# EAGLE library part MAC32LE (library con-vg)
CONNECTOR male, 32 pins, single, type D, rows AC, grid 5.08 mm with mounting clip
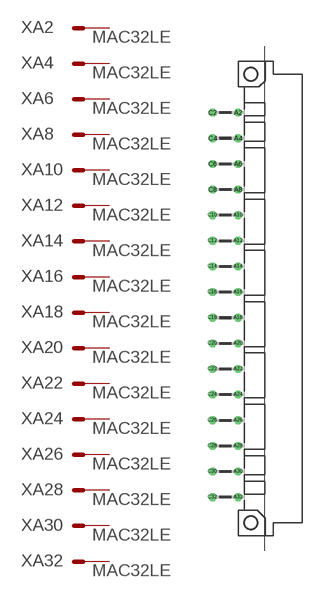
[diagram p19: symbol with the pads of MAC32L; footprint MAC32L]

Designator prefix X; gates A2=M A4=M A6=M A8=M A10=M A12=M A14=M A16=M A18=M A20=M A22=M A24=M A26=M A28=M A30=M A32=M C2=M C4=M C6=M C8=M C10=M C12=M C14=M C16=M C18=M C20=M C22=M C24=M C26=M C28=M C30=M C32=M

## MAC32LE  [MAC32L]
A2  A2:S  pas
A4  A4:S  pas
A6  A6:S  pas
A8  A8:S  pas
A10  A10:S  pas
A12  A12:S  pas
A14  A14:S  pas
A16  A16:S  pas
A18  A18:S  pas
A20  A20:S  pas
A22  A22:S  pas
A24  A24:S  pas
A26  A26:S  pas
A28  A28:S  pas
A30  A30:S  pas
A32  A32:S  pas
C2  C2:S  pas
C4  C4:S  pas
C6  C6:S  pas
C8  C8:S  pas
C10  C10:S  pas
C12  C12:S  pas
C14  C14:S  pas
C16  C16:S  pas
C18  C18:S  pas
C20  C20:S  pas
C22  C22:S  pas
C24  C24:S  pas
C26  C26:S  pas
C28  C28:S  pas
C30  C30:S  pas
C32  C32:S  pas

## Footprint MAC32L (pad centres in mm)
CONNECTOR male, 32 pins, type D, rows AC, grid 5.08 mm with mounting clip
drill 1.016 octagon: A2 -2.54,36.83; A4 -2.54,31.75; A6 -2.54,26.67; A8 -2.54,21.59; A10 -2.54,16.51; A12 -2.54,11.43; A14 -2.54,6.35; A16 -2.54,1.27; A18 -2.54,-3.81; A20 -2.54,-8.89; A22 -2.54,-13.97; A24 -2.54,-19.05; A26 -2.54,-24.13; A28 -2.54,-29.21; A30 -2.54,-34.29; A32 -2.54,-39.37; C2 -7.62,36.83; C4 -7.62,31.75; C6 -7.62,26.67; C8 -7.62,21.59; C10 -7.62,16.51; C12 -7.62,11.43; C14 -7.62,6.35; C16 -7.62,1.27; C18 -7.62,-3.81; C20 -7.62,-8.89; C22 -7.62,-13.97; C24 -7.62,-19.05; C26 -7.62,-24.13; C28 -7.62,-29.21; C30 -7.62,-34.29; C32 -7.62,-39.37
hole 2.794 at 0,44.45
hole 2.794 at 0,-44.45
